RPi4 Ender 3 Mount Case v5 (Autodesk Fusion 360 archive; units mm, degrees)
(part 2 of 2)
sketch "Skizze9" plane through (0, 0, 1) normal (0, 0, 1) x axis (1, 0, 0)
  line L1 (52.4999, 24.6406) -> (52.4999, -25)
  line L2 (-29.5, 28) -> (49.5215, 28)
  line L3 (-29.5, -28) -> (49.4999, -28)
  line L4 (-32.5, -25.0196) -> (-32.5, 24.5)
  line L5 (-32.5, 24.5) -> (-32.5, 25)
  line L6 (52.4999, 24.6406) -> (52.4999, -25)
  line L7 (-29.5, 28) -> (49.5215, 28)
  line L8 (-32.5, -25) -> (-32.5, 25)
  line L9 (49.4999, -28) -> (-29.5, -28)
  line L10 (-25.8, -29.25) -> (-16.8, -29.25)
  line L11 (-25.8, -21.75) -> (-25.8, -29.25)
  line L12 (-16.8, -21.75) -> (-25.8, -21.75)
  line L13 (-16.8, -29.25) -> (-16.8, -21.75)
  line L14 (-25.8, -21.75) -> (-16.8, -29.25)
  line L15 (-16.8, -21.75) -> (-25.8, -29.25)
  line L16 (-10.05, -29.3) -> (-2.95, -29.3)
  line L17 (-10.05, -21.3) -> (-10.05, -29.3)
  line L18 (-2.95, -21.3) -> (-10.05, -21.3)
  line L19 (-2.95, -29.3) -> (-2.95, -21.3)
  line L20 (-10.05, -21.3) -> (-2.95, -29.3)
  line L21 (-2.95, -21.3) -> (-10.05, -29.3)
  line L22 (3.45, -29.3) -> (10.55, -29.3)
  line L23 (3.45, -21.3) -> (3.45, -29.3)
  line L24 (10.55, -21.3) -> (3.45, -21.3)
  line L25 (10.55, -29.3) -> (10.55, -21.3)
  line L26 (3.45, -21.3) -> (10.55, -29.3)
  line L27 (10.55, -21.3) -> (3.45, -29.3)
  line L28 (25, -28) -> (18, -28)
  line L29 (25, -16.5) -> (25, -28)
  line L30 (18, -16.5) -> (25, -16.5)
  line L31 (18, -28) -> (18, -16.5)
  line L32 (25, -16.5) -> (18, -28)
  line L33 (18, -16.5) -> (25, -28)
  line L34 (37.9999, -26.35) -> (55.4999, -26.35)
  line L35 (37.9999, -11.65) -> (37.9999, -26.35)
  line L36 (55.4999, -11.65) -> (37.9999, -11.65)
  line L37 (55.4999, -26.35) -> (55.4999, -11.65)
  line L38 (37.9999, -11.65) -> (55.4999, -26.35)
  line L39 (55.4999, -11.65) -> (37.9999, -26.35)
  line L40 (37.9999, -8.35) -> (55.4999, -8.35)
  line L41 (37.9999, 6.35) -> (37.9999, -8.35)
  line L42 (55.4999, 6.35) -> (37.9999, 6.35)
  line L43 (55.4999, -8.35) -> (55.4999, 6.35)
  line L44 (37.9999, 6.35) -> (55.4999, -8.35)
  line L45 (55.4999, 6.35) -> (37.9999, -8.35)
  line L46 (33.9999, 9.75) -> (55.4999, 9.75)
  line L47 (33.9999, 25.75) -> (33.9999, 9.75)
  line L48 (55.4999, 25.75) -> (33.9999, 25.75)
  line L49 (55.4999, 9.75) -> (55.4999, 25.75)
  line L50 (33.9999, 25.75) -> (55.4999, 9.75)
  line L51 (55.4999, 25.75) -> (33.9999, 9.75)
  line L52 (-25.4, 22) -> (25.4, 22)
  line L53 (-25.4, 27) -> (-25.4, 22)
  line L54 (25.4, 27) -> (-25.4, 27)
  line L55 (25.4, 22) -> (25.4, 27)
  line L56 (-25.4, 27) -> (25.4, 22)
  line L57 (25.4, 27) -> (-25.4, 22)
  line L58 (29, 24.5) -> (-29, 24.5)
  line L59 (-29.75, -11) -> (-27.25, -11)
  line L60 (-29.75, 11) -> (-29.75, -11)
  line L61 (-27.25, 11) -> (-29.75, 11)
  line L62 (-27.25, -11) -> (-27.25, 11)
  line L63 (-29.75, 11) -> (-27.25, -11)
  line L64 (-27.25, 11) -> (-29.75, -11)
  line L65 (-10.75, -3) -> (4.25, -3)
  line L66 (-10.75, 12) -> (-10.75, -3)
  line L67 (4.25, 12) -> (-10.75, 12)
  line L68 (4.25, -3) -> (4.25, 12)
  line L69 (-10.75, 12) -> (4.25, -3)
  line L70 (4.25, 12) -> (-10.75, -3)
  line L71 (12.75, -27.5) -> (15.25, -27.5)
  line L72 (12.75, -5.5) -> (12.75, -27.5)
  line L73 (15.25, -5.5) -> (12.75, -5.5)
  line L74 (15.25, -27.5) -> (15.25, -5.5)
  line L75 (12.75, -5.5) -> (15.25, -27.5)
  line L76 (15.25, -5.5) -> (12.75, -27.5)
  line L77 (-24.4, -8.625) -> (-16.6, -8.625)
  line L78 (-24.4, -6.375) -> (-24.4, -8.625)
  line L79 (-16.6, -6.375) -> (-24.4, -6.375)
  line L80 (-16.6, -8.625) -> (-16.6, -6.375)
  line L81 (-24.4, -6.375) -> (-16.6, -8.625)
  line L82 (-16.6, -6.375) -> (-24.4, -8.625)
  line L83 (3.45, -29.3) -> (-2.95, -29.3)
  line L84 (3.45, -21.3) -> (-2.95, -21.3)
  line L85 (55.4999, -8.35) -> (55.4999, -11.65)
  line L86 (55.4999, 9.75) -> (55.4999, 6.35)
  line L87 (26.4, 15.76) -> (31.6, 15.76)
  line L88 (26.4, 20.96) -> (26.4, 15.76)
  line L89 (31.6, 20.96) -> (26.4, 20.96)
  line L90 (31.6, 15.76) -> (31.6, 20.96)
  line L91 (26.4, 20.96) -> (31.6, 15.76)
  line L92 (31.6, 20.96) -> (26.4, 15.76)
  line L93 (29, 18.36) -> (29, 24.5)
  line L94 (52.4999, 0) -> (-32.5, 0)
  line L95 (29, -24.5) -> (-29, -24.5)
  arc A1 centre (49.5215, 25) radius 3 clockwise from (49.5215, 28) to (52.4999, 24.6406)
  arc A2 centre (49.4999, -25) radius 3 clockwise from (52.4999, -25) to (49.4999, -28)
  circle C1 centre (29, -24.5) radius 1.3
  arc A3 centre (-29.5, 25) radius 3 clockwise from (-32.5, 25) to (-29.5, 28)
  arc A4 centre (-29.5, -25) radius 3 clockwise from (-29.5, -28) to (-32.5, -25)
  circle C2 centre (29, 24.5) radius 1.3
  circle C3 centre (-29, 24.5) radius 1.3
  circle C4 centre (-29, -24.5) radius 1.3
  circle C5 centre (29, -24.5) radius 1.3
  circle C6 centre (29, 24.5) radius 1.3
  circle C7 centre (-29, -24.5) radius 1.3
  circle C8 centre (-29, 24.5) radius 1.3
  arc A5 centre (49.4999, -25) radius 3 clockwise from (52.4999, -25) to (49.4999, -28)
  arc A6 centre (49.5215, 25) radius 3 clockwise from (49.5215, 28) to (52.4999, 24.6406)
  arc A7 centre (-29.5, 25) radius 3 clockwise from (-32.5, 25) to (-29.5, 28)
  arc A8 centre (-29.5, -25) radius 3 clockwise from (-29.5, -28) to (-32.5, -25)
  point P48 (-21.3, -25.5)
  point P53 (-6.5, -25.3)
  point P58 (7, -25.3)
  point P63 (21.5, -22.25)
  point P60 (25, -28)
  point P68 (46.7499, -19)
  point P73 (46.7499, -1)
  point P78 (44.7499, 17.75)
  point P83 (0, 24.5)
  point P24 (-29, 24.5)
  point P84 (-29, 24.5)
  point P23 (29, 24.5)
  point P85 (29, 24.5)
  point P90 (-28.5, 0)
  point P95 (-3.25, 4.5)
  point P100 (14, -16.5)
  point P105 (-20.5, -7.5)
  point P110 (29, 18.36)
  point P29 (29, 24.5)
  point P111 (29, 24.5)
  point P112 (29, 18.36)
  point P113 (-32.5, 0)
  point P114 (52.4999, 0)
  point P25 (-29, -24.5)
  point P115 (-29, -24.5)
  point P28 (29, -24.5)
  point P116 (29, -24.5)
  point P66 (37.9999, -11.65)
  point P67 (55.4999, -11.65)
  point P64 (55.4999, -26.35)
  point P61 (25, -16.5)
  point P62 (18, -16.5)
  point P76 (33.9999, 25.75)
  point P77 (55.4999, 25.75)
  point P75 (33.9999, 9.75)
  point P107 (26.4, 15.76)
  point P108 (26.4, 20.96)
  point P109 (31.6, 20.96)
  point P69 (55.4999, -8.35)
  point P70 (37.9999, -8.35)
  point P72 (55.4999, 6.35)
  point P44 (-16.8, -29.25)
  point P45 (-25.8, -29.25)
  point P47 (-16.8, -21.75)
  point P96 (15.25, -27.5)
  point P99 (15.25, -5.5)
  point P98 (12.75, -5.5)
  point P93 (-10.75, 12)
  point P94 (4.25, 12)
  point P79 (25.4, 22)
  point P82 (25.4, 27)
  point P81 (-25.4, 27)
  point P103 (-24.4, -6.375)
  point P104 (-16.6, -6.375)
  point P101 (-16.6, -8.625)
  point P88 (-29.75, 11)
  point P89 (-27.25, 11)
  point P86 (-27.25, -11)
  perpendicular L10 L11
  parallel L10 L12
  parallel L11 L13
  horizontal L10
  coincident L14 P48
  coincident L15 P48
  perpendicular L16 L17
  parallel L16 L18
  parallel L17 L19
  horizontal L16
  coincident L20 P53
  coincident L21 P53
  perpendicular L22 L23
  parallel L22 L24
  parallel L23 L25
  horizontal L22
  coincident L26 P58
  coincident L27 P58
  perpendicular L28 L29
  parallel L28 L30
  parallel L29 L31
  horizontal L28
  coincident L32 P63
  coincident L33 P63
  coincident L3 P60
  perpendicular L34 L35
  parallel L34 L36
  parallel L35 L37
  horizontal L34
  coincident L38 P68
  coincident L39 P68
  perpendicular L40 L41
  parallel L40 L42
  parallel L41 L43
  horizontal L40
  coincident L44 P73
  coincident L45 P73
  perpendicular L46 L47
  parallel L46 L48
  parallel L47 L49
  horizontal L46
  coincident L50 P78
  coincident L51 P78
  perpendicular L52 L53
  parallel L52 L54
  parallel L53 L55
  horizontal L52
  coincident L56 P83
  coincident L57 P83
  coincident P24 P84
  coincident P23 P85
  coincident P83 L58
  perpendicular L59 L60
  parallel L59 L61
  parallel L60 L62
  horizontal L59
  coincident L63 P90
  coincident L64 P90
  perpendicular L65 L66
  parallel L65 L67
  parallel L66 L68
  horizontal L65
  coincident L69 P95
  coincident L70 P95
  perpendicular L71 L72
  parallel L71 L73
  parallel L72 L74
  horizontal L71
  coincident L75 P100
  coincident L76 P100
  perpendicular L77 L78
  parallel L77 L79
  parallel L78 L80
  horizontal L77
  coincident L81 P105
  coincident L82 P105
  horizontal L83
  horizontal L84
  perpendicular L42 L86
  vertical L85
  perpendicular L87 L88
  parallel L87 L89
  parallel L88 L90
  horizontal L87
  coincident L91 P110
  coincident L92 P110
  midpoint L70 P95
  coincident P29 P111
  coincident P110 P112
  vertical L93
  equal L67 L68
  coincident L8 P113
  coincident L1 P114
  horizontal L94
  coincident P25 P115
  coincident P28 P116
  symmetric L58 L94 L95
  coincident P90 L94
  dimension "d66" distance L3 P68 = 9
  dimension "d67" distance L3 P73 = 27
  dimension "d68" distance L3 P78 = 45.75
  dimension "d69" distance P83 P84 = 29
  dimension "d70" distance P25 P48 = 7.7
  dimension "d71" distance P48 P53 = 14.8
  dimension "d72" distance P53 P58 = 13.5
  dimension "d73" distance L17 L19 = 7.1
  dimension "d74" distance L23 L25 = 7.1
  dimension "d75" distance L16 L18 = 8
  dimension "d76" distance P66 P67 = 17.5
  dimension "d77" distance P64 P67 = 14.7
  dimension "d78" distance L3 L22 = 1.3
  dimension "d79" distance P60 P61 = 11.5
  dimension "d80" distance P61 P62 = 7
  dimension "d82" distance P58 P100 = 7
  dimension "d84" distance P63 P100 = 7.5
  dimension "d85" distance L1 L85 = 3
  dimension "d86" distance P76 P77 = 21.5
  dimension "d87" distance P75 P76 = 16
  dimension "d88" distance P107 P108 = 5.2
  dimension "d89" distance P108 P109 = 5.2
  dimension "d90" distance L3 P100 = 11.5
  dimension "d91" distance P69 P70 = 17.5 (= "d76")
  dimension "d92" distance P69 P72 = 14.7 (= "d77")
  dimension "d122" distance L4 P105 = 12
  dimension "d123" distance L3 P105 = 20.5
  dimension "d124" distance L4 P90 = 4
  dimension "d125" distance L3 P95 = 32.5
  dimension "d126" distance P84 P95 = 25.75
  dimension "d127" distance L3 L10 = 1.25
  dimension "d128" distance P44 P45 = 9
  dimension "d129" distance P44 P47 = 7.5
  dimension "d130" distance P96 P99 = 22
  dimension "d131" distance P98 P99 = 2.5
  dimension "d133" distance L58 P110 = 6.14
  dimension "d134" distance P93 P94 = 15
  dimension "d137" distance P79 P82 = 5
  dimension "d138" distance P81 P82 = 50.8
  dimension "d139" distance P103 P104 = 7.8
  dimension "d140" distance P101 P104 = 2.25
  dimension "d141" distance P88 P89 = 2.5
  dimension "d142" distance P86 P89 = 22
extrude "Extrusion8" new body sketch "Skizze9" profile of L9 L10 L11 L12 L13 along normal blind 3.2 bodies "Power USB C"
extrude "Extrusion9" new body sketch "Skizze9" profile of L9 L16 L17 L18 L19 L22 L23 L24 L25 along normal blind 3.3 bodies "Micro HDMI 1", "Micro HDMI 2"
extrude "Extrusion10" new body sketch "Skizze9" profile of L59 L60 L61 L62 L71 L72 L73 L74 along normal blind 5.5 bodies "Kamera", "Display"
extrude "Extrusion11" new body sketch "Skizze9" profile of L9 L28 L29 L30 L31 along normal blind 6 bodies "3.5 mm Audio"
extrude "Extrusion12" new body sketch "Skizze9" profile of A5 L6 L34 L35 L36 L37 L40 L41 L42 L43 along normal blind 16.5 bodies "USB 2.0", "USB 3.0"
extrude "Extrusion13" new body sketch "Skizze9" profile of A1 L6 A6 L46 L47 L48 L49 along normal blind 13.5 bodies "Ethernet"
extrude "Extrusion14" new body sketch "Skizze9" profile of L52 L53 L54 L55 L87 L88 L89 L90 along normal blind 8.5 bodies "GPIO 40", "PoE"
extrude "Extrusion15" new body sketch "Skizze9" profile of L65 L66 L67 L68 along normal blind 2.4 bodies "Processor"
sketch "Skizze10" plane through (0, -28, 0) normal (0, -1, 0) x axis (1, 0, 0)
  line L1 (25, 1) -> (18, 1)
  line L2 (25, 7) -> (25, 1)
  line L3 (18, 7) -> (25, 7)
  line L4 (18, 1) -> (18, 7)
  line L5 (25, 1) -> (18, 7)
  line L6 (18, 1) -> (25, 7)
  circle C1 centre (21.5, 4) radius 3
  point P5 (18, 7)
  point P7 (18, 7)
  point P3 (25, 1)
  point P8 (25, 1)
  point P4 (25, 7)
  point P9 (25, 7)
  point P2 (18, 1)
  point P10 (18, 1)
  point P6 (21.5, 4)
  tangent L1 C1
  coincident P5 P7
  coincident P3 P8
  coincident P4 P9
  coincident P2 P10
  coincident P6 L6
  coincident P6 L5
extrude "Extrusion16" add sketch "Skizze10" profile of C1 along normal blind 2.5
fillet "Abrundung1" radius 1.5
chamfer "Fase" distance 1
fillet "Abrundung2" radius 0.5
component_from_bodies "Körper->Berechn4"
component_from_bodies "Körper->Berechn5"
component_from_bodies "Körper->Berechn6"
component_from_bodies "Körper->Berechn7"
component_from_bodies "Körper->Berechn8"
component_from_bodies "Körper->Berechn9"
component_from_bodies "Körper->Berechn10"
component_from_bodies "Körper->Berechn11"
component_from_bodies "Körper->Berechn12"
component_from_bodies "Körper->Berechn13"
component_from_bodies "Körper->Berechn14"
component_from_bodies "Körper->Berechn15"
as_built_joint "Bestand"
ground "Fixieren"
sketch "Skizze11" plane through (0, 0, 0) normal (0, 0, -1) x axis (1, 0, 0)
  line L1 (-29.5, 28) -> (49.4985, 28)
  line L2 (-32.5, -25) -> (-32.5, 25)
  line L3 (49.4985, -28) -> (-29.5, -28)
  line L4 (52.4985, 25) -> (52.4985, -25)
  line L5 (-29, -24.5) -> (-29, 24.5)
  line L6 (-35, 5.5) -> (-23, 5.5)
  line L7 (-35, -5.5) -> (-35, 5.5)
  line L8 (-23, -5.5) -> (-35, -5.5)
  line L9 (-23, 5.5) -> (-23, -5.5)
  line L10 (-35, -5.5) -> (-23, 5.5)
  line L11 (-23, -5.5) -> (-35, 5.5)
  circle C1 centre (29, 24.5) radius 1.35
  circle C2 centre (-29, 24.5) radius 1.35
  circle C3 centre (-29, -24.5) radius 1.35
  circle C4 centre (29, -24.5) radius 1.35
  arc A1 centre (49.4985, 25) radius 3 clockwise from (49.4985, 28) to (52.4985, 25)
  arc A2 centre (-29.5, 25) radius 3 clockwise from (-32.5, 25) to (-29.5, 28)
  arc A3 centre (-29.5, -25) radius 3 clockwise from (-29.5, -28) to (-32.5, -25)
  arc A4 centre (49.4985, -25) radius 3 clockwise from (52.4985, -25) to (49.4985, -28)
  point P3 (-29, 24.5)
  point P18 (-29, 24.5)
  point P4 (-29, -24.5)
  point P19 (-29, -24.5)
  point P24 (-29, 0)
  point P21 (-35, 5.5)
  point P22 (-35, -5.5)
  point P23 (-23, -5.5)
  coincident P3 P18
  coincident P4 P19
  perpendicular L6 L7
  parallel L6 L8
  parallel L7 L9
  horizontal L6
  coincident L10 P24
  coincident L11 P24
  midpoint L5 P24
  dimension "d114" distance P21 P22 = 11
  dimension "d115" distance P22 P23 = 12
extrude "Extrusion1" new body sketch "Skizze11" profile of L2 L6 L7 L8 L9 along normal blind 1.2
fillet "Abrundung1" radius 0.6
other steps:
base_feature "Basiselement1" bodies "Power USB C"
base_feature "Basiselement1" bodies "Micro HDMI 2"
base_feature "Basiselement1" bodies "3.5 mm Audio"
base_feature "Basiselement1" bodies "Micro HDMI 1"
base_feature "Basiselement1" bodies "USB 2.0"
base_feature "Basiselement1" bodies "Display"
base_feature "Basiselement1" bodies "Processor"
base_feature "Basiselement1" bodies "Ethernet"
base_feature "Basiselement1" bodies "Kamera"
base_feature "Basiselement1" bodies "GPIO 40"
base_feature "Basiselement1" bodies "USB 3.0"
base_feature "Basiselement1" bodies "PoE"
base_feature "Basiselement1"
create_component "Komponente erstellen3"
remove_body "Körper entfernen3"
create_component "Komponente erstellen4"
remove_body "Körper entfernen4"
create_component "Komponente erstellen5"
remove_body "Körper entfernen5"
create_component "Komponente erstellen6"
remove_body "Körper entfernen6"
create_component "Komponente erstellen7"
remove_body "Körper entfernen7"
create_component "Komponente erstellen8"
remove_body "Körper entfernen8"
create_component "Komponente erstellen9"
remove_body "Körper entfernen9"
create_component "Komponente erstellen10"
remove_body "Körper entfernen10"
create_component "Komponente erstellen11"
remove_body "Körper entfernen11"
create_component "Komponente erstellen12"
remove_body "Körper entfernen12"
create_component "Komponente erstellen13"
remove_body "Körper entfernen13"
create_component "Komponente erstellen14"
remove_body "Körper entfernen14"
create_component "Komponente erstellen15"
remove_body "Körper entfernen15"
named bodies: "Power USB C", "Micro HDMI 1", "Micro HDMI 2", "Kamera", "Display", "3.5 mm Audio", "USB 2.0", "USB 3.0", "Ethernet", "GPIO 40", "PoE", "Processor"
